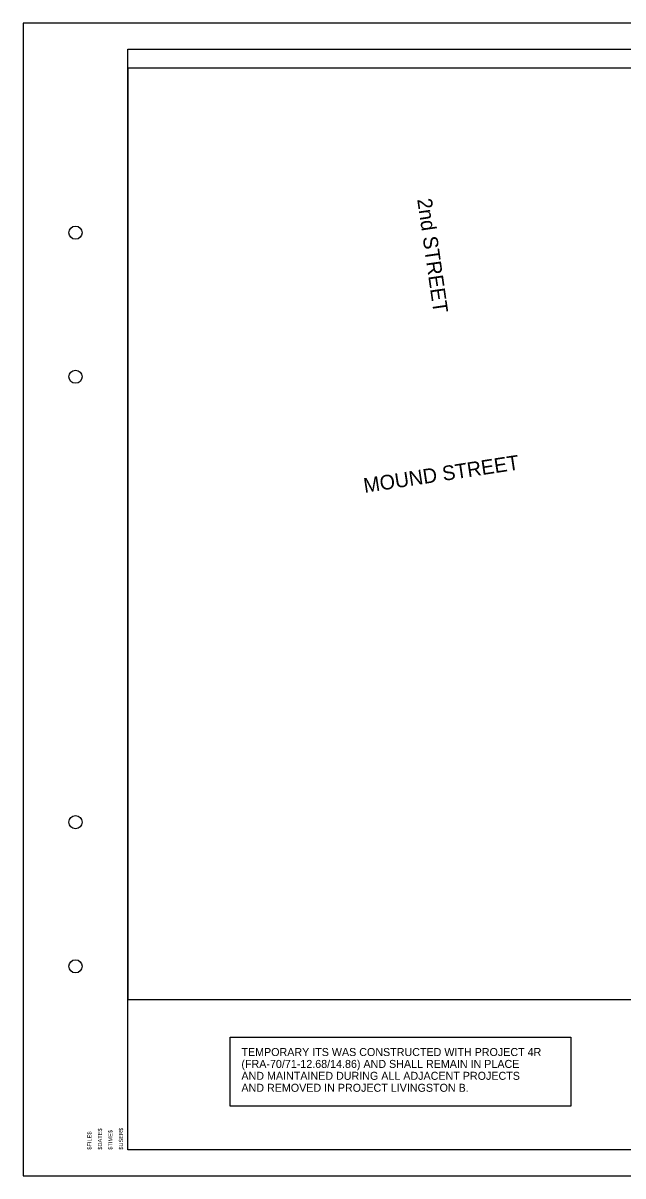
# Model space of a CAD drawing. Extents: x 1826739 to 1830139, y 710816 to 713016.
# Drawn here: x 1826739 to 1827883, y 710816 to 713016 of the extents above; entities that cross this region are included whole.
import ezdxf

# ---------------------------------------------------------------- set-up
doc = ezdxf.new("R2010")
doc.units = 0
for name, color, linetype in [('POOLS', 7, 'Continuous'), ('SH_Border', 7, 'Continuous'), ('SH_Cut_Line', 7, 'Continuous'), ('SH_Text', 7, 'Continuous'), ('TX_P_100', 7, 'Continuous'), ('TX_P_Misc', 7, 'Continuous')]:
    doc.layers.add(name, color=color, linetype=linetype)

msp = doc.modelspace()

# ---------------------------------------------------------------- linework, layer by layer
at = {"layer": 'POOLS'}
msp.add_lwpolyline([(1826938.7, 711152.7), (1829988.7, 711152.7), (1829988.7, 712929.8), (1826938.7, 712929.8)], close=True, dxfattribs=at)
at = {"layer": 'SH_Border'}
for points in [[(1826938.7, 712965.9), (1830088.7, 712965.9), (1830088.7, 710865.9), (1826938.7, 710865.9)], [(1827133.8, 711080.5), (1827783, 711080.5), (1827783, 710948.8), (1827133.8, 710948.8)]]:
    msp.add_lwpolyline(points, close=True, dxfattribs=at)
for centre in [(1826838.7, 712615.9), (1826838.7, 712340.9), (1826838.7, 711490.9), (1826838.7, 711215.9)]:
    msp.add_circle(centre, 12.5, dxfattribs=at)
at = {"layer": 'SH_Cut_Line'}
msp.add_lwpolyline([(1826738.7, 710815.9), (1830138.7, 710815.9), (1830138.7, 713015.9), (1826738.7, 713015.9)], close=True, dxfattribs=at)

# ---------------------------------------------------------------- texts
at = {"layer": 'SH_Text'}
for s, p in [('TEMPORARY ITS WAS CONSTRUCTED WITH PROJECT 4R', (1827155.1, 711044.7)), ('(FRA-70/71-12.68/14.86) AND SHALL REMAIN IN PLACE', (1827155.1, 711022)), ('AND MAINTAINED DURING ALL ADJACENT PROJECTS', (1827155.1, 710999.3)), ('AND REMOVED IN PROJECT LIVINGSTON B.', (1827155.1, 710976.5))]:
    msp.add_text(s, height=15.273, dxfattribs=at).set_placement(p)
at = {"layer": 'TX_P_100'}
for s, rotation, p in [('2nd STREET', 278.2126, (1827490.2, 712679.5)), ('MOUND STREET', 8.6541, (1827390.1, 712119.2))]:
    msp.add_text(s, height=28, rotation=rotation, dxfattribs=at).set_placement(p)
at = {"layer": 'TX_P_Misc'}
for s, p in [('$FILE$', (1826869.2, 710865.9)), ('$DATE$', (1826889.2, 710865.9)), ('$TIME$', (1826909.2, 710865.9)), ('$USER$', (1826929.2, 710865.9))]:
    msp.add_text(s, height=7.8, rotation=90, dxfattribs=at).set_placement(p)

doc.saveas('drawing.dxf')
